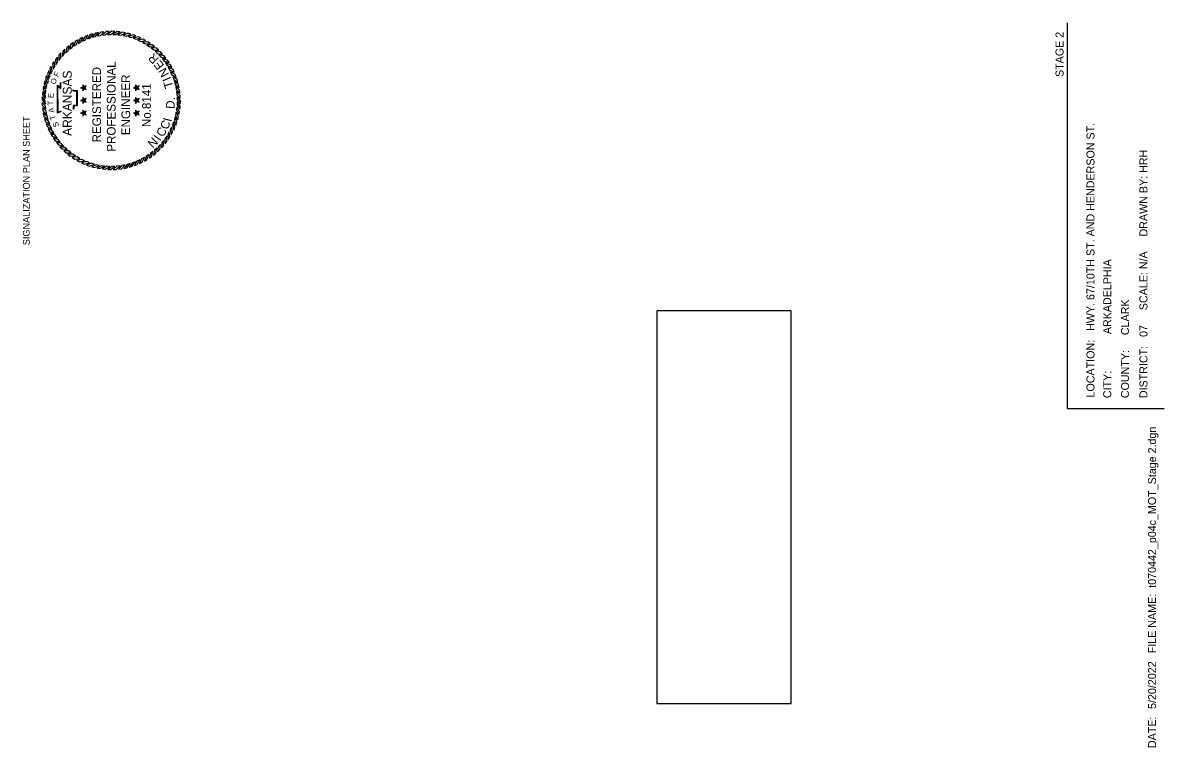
# Model space of a CAD drawing. Extents: x 610547 to 611161, y 419122 to 420064.
# Drawn here: x 610558 to 611161, y 419682 to 420064 of the extents above; entities that cross this region are included whole.
import ezdxf

# ---------------------------------------------------------------- set-up
doc = ezdxf.new("R2010")
doc.units = 0
for name, color, linetype in [('G-ANNO-SYMB', 7, 'Continuous'), ('G-ANNO-TEXT', 7, 'Continuous'), ('Level 10', 7, 'Continuous'), ('Level 57', 7, 'Continuous'), ('No Plot', 7, 'Continuous')]:
    doc.layers.add(name, color=color, linetype=linetype)

msp = doc.modelspace()

# ---------------------------------------------------------------- linework, layer by layer
at = {"layer": 'G-ANNO-SYMB'}
for points in [[(610592.78, 420057.58), (610591.32, 420057.02), (610589.94, 420054.58), (610591.48, 420055.28)], [(610595.51, 420058.43), (610594.01, 420057.99), (610592.45, 420055.67), (610594.04, 420056.25)], [(610598.31, 420059.07), (610596.77, 420058.75), (610595.03, 420056.56), (610596.67, 420057.01)], [(610601.14, 420059.49), (610599.58, 420059.29), (610597.68, 420057.24), (610599.34, 420057.56)], [(610604, 420059.68), (610602.43, 420059.6), (610600.37, 420057.72), (610602.05, 420057.9)], [(610606.86, 420059.65), (610605.29, 420059.7), (610603.09, 420057.98), (610604.78, 420058.03)], [(610609.71, 420059.4), (610608.15, 420059.56), (610605.82, 420058.02), (610607.52, 420057.94)], [(610612.54, 420058.92), (610611, 420059.21), (610608.55, 420057.85), (610610.23, 420057.64)], [(610615.32, 420058.22), (610613.8, 420058.63), (610611.26, 420057.47), (610612.92, 420057.13)], [(610618.03, 420057.31), (610616.55, 420057.83), (610613.93, 420056.88), (610615.55, 420056.4)], [(610582.77, 420052.11), (610581.54, 420051.12), (610580.99, 420048.38), (610582.24, 420049.52)], [(610585.1, 420053.77), (610583.81, 420052.88), (610583.04, 420050.19), (610584.37, 420051.23)], [(610587.56, 420055.24), (610586.2, 420054.45), (610585.22, 420051.84), (610586.64, 420052.77)], [(610590.12, 420056.51), (610588.71, 420055.84), (610587.53, 420053.3), (610589.01, 420054.12)], [(610620.66, 420056.18), (610619.23, 420056.82), (610616.54, 420056.08), (610618.12, 420055.48)], [(610623.2, 420054.85), (610621.82, 420055.61), (610619.08, 420055.07), (610620.61, 420054.35)], [(610625.63, 420053.33), (610624.31, 420054.19), (610621.54, 420053.87), (610623.01, 420053.03)], [(610627.93, 420051.62), (610626.68, 420052.58), (610623.89, 420052.48), (610625.29, 420051.53)], [(610576.64, 420046.11), (610575.68, 420044.87), (610575.78, 420042.07), (610576.73, 420043.47)], [(610578.52, 420048.27), (610577.47, 420047.1), (610577.35, 420044.31), (610578.41, 420045.63)], [(610580.57, 420050.27), (610579.43, 420049.19), (610579.09, 420046.42), (610580.25, 420047.65)], [(610630.08, 420049.74), (610628.92, 420050.79), (610626.13, 420050.92), (610627.45, 420049.86)], [(610632.09, 420047.69), (610631.01, 420048.83), (610628.24, 420049.18), (610629.47, 420048.02)], [(610633.92, 420045.5), (610632.94, 420046.72), (610630.2, 420047.28), (610631.34, 420046.02)], [(610573.41, 420041.38), (610572.66, 420040.01), (610573.19, 420037.26), (610573.91, 420038.8)], [(610574.93, 420043.81), (610574.07, 420042.5), (610574.39, 420039.72), (610575.23, 420041.19)], [(610635.58, 420043.16), (610634.7, 420044.46), (610632.01, 420045.23), (610633.05, 420043.89)], [(610637.05, 420040.7), (610636.27, 420042.06), (610633.65, 420043.04), (610634.58, 420041.63)], [(610638.33, 420038.14), (610637.65, 420039.56), (610635.12, 420040.74), (610635.94, 420039.25)], [(610570.04, 420033.5), (610569.63, 420031.98), (610570.79, 420029.44), (610571.14, 420031.1)], [(610570.96, 420036.21), (610570.43, 420034.73), (610571.39, 420032.11), (610571.86, 420033.74)], [(610572.08, 420038.85), (610571.44, 420037.41), (610572.19, 420034.72), (610572.78, 420036.31)], [(610639.39, 420035.48), (610638.83, 420036.95), (610636.4, 420038.32), (610637.1, 420036.78)], [(610640.25, 420032.75), (610639.81, 420034.25), (610637.49, 420035.82), (610638.06, 420034.22)], [(610568.87, 420027.9), (610568.7, 420026.34), (610570.24, 420024.01), (610570.32, 420025.7)], [(610569.34, 420030.72), (610569.05, 420029.18), (610570.41, 420026.73), (610570.62, 420028.41)], [(610590.52, 420029.89), (610590, 420030.27), (610588.85, 420029.89), (610590, 420029.52)], [(610590.52, 420029.89), (610590.71, 420030.5), (610590, 420031.48), (610590, 420030.27)], [(610590.52, 420029.89), (610590, 420029.52), (610590, 420028.31), (610590.71, 420029.29)], [(610590.52, 420029.89), (610591.15, 420029.89), (610591.86, 420030.87), (610590.71, 420030.5)], [(610590.52, 420029.89), (610590.71, 420029.29), (610591.86, 420028.91), (610591.15, 420029.89)], [(610618.45, 420029.89), (610617.93, 420030.27), (610616.78, 420029.89), (610617.93, 420029.52)], [(610618.45, 420029.89), (610618.64, 420030.5), (610617.93, 420031.48), (610617.93, 420030.27)], [(610618.45, 420029.89), (610617.93, 420029.52), (610617.93, 420028.31), (610618.64, 420029.29)], [(610618.45, 420029.89), (610619.08, 420029.89), (610619.79, 420030.87), (610618.64, 420030.5)], [(610618.45, 420029.89), (610618.64, 420029.29), (610619.79, 420028.91), (610619.08, 420029.89)], [(610640.89, 420029.96), (610640.57, 420031.49), (610638.38, 420033.23), (610638.83, 420031.6)], [(610641.31, 420027.12), (610641.1, 420028.68), (610639.06, 420030.58), (610639.38, 420028.92)], [(610641.5, 420024.27), (610641.42, 420025.83), (610639.53, 420027.89), (610639.72, 420026.21)], [(610568.61, 420025.04), (610568.57, 420023.48), (610570.29, 420021.27), (610570.23, 420022.97)], [(610568.58, 420022.18), (610568.66, 420020.61), (610570.55, 420018.55), (610570.36, 420020.24)], [(610590.52, 420023.22), (610590, 420023.6), (610588.85, 420023.22), (610590, 420022.85)], [(610590.52, 420023.22), (610590.71, 420023.83), (610590, 420024.81), (610590, 420023.6)], [(610590.52, 420023.22), (610590, 420022.85), (610590, 420021.64), (610590.71, 420022.62)], [(610590.52, 420023.22), (610591.15, 420023.22), (610591.86, 420024.2), (610590.71, 420023.83)], [(610590.52, 420023.22), (610590.71, 420022.62), (610591.86, 420022.24), (610591.15, 420023.22)], [(610618.45, 420023.22), (610617.93, 420023.6), (610616.78, 420023.22), (610617.93, 420022.85)], [(610618.45, 420023.22), (610618.64, 420023.83), (610617.93, 420024.81), (610617.93, 420023.6)], [(610618.45, 420023.22), (610617.93, 420022.85), (610617.93, 420021.64), (610618.64, 420022.62)], [(610618.45, 420023.22), (610619.08, 420023.22), (610619.79, 420024.2), (610618.64, 420023.83)], [(610618.45, 420023.22), (610618.64, 420022.62), (610619.79, 420022.24), (610619.08, 420023.22)], [(610641.21, 420018.55), (610641.38, 420020.11), (610639.84, 420022.44), (610639.76, 420020.75)], [(610641.47, 420021.4), (610641.51, 420022.97), (610639.79, 420025.17), (610639.85, 420023.48)], [(610568.77, 420019.32), (610568.98, 420017.77), (610571.02, 420015.86), (610570.7, 420017.52)], [(610569.19, 420016.49), (610569.51, 420014.95), (610571.7, 420013.21), (610571.25, 420014.85)], [(610590.52, 420016.55), (610590, 420016.93), (610588.85, 420016.55), (610590, 420016.18)], [(610590.52, 420016.55), (610590.71, 420017.16), (610590, 420018.14), (610590, 420016.93)], [(610590.52, 420016.55), (610590, 420016.18), (610590, 420014.97), (610590.71, 420015.95)], [(610590.52, 420016.55), (610591.15, 420016.55), (610591.86, 420017.53), (610590.71, 420017.16)], [(610590.52, 420016.55), (610590.71, 420015.95), (610591.86, 420015.57), (610591.15, 420016.55)], [(610618.45, 420016.55), (610617.93, 420016.93), (610616.78, 420016.55), (610617.93, 420016.18)], [(610618.45, 420016.55), (610618.64, 420017.16), (610617.93, 420018.14), (610617.93, 420016.93)], [(610618.45, 420016.55), (610617.93, 420016.18), (610617.93, 420014.97), (610618.64, 420015.95)], [(610618.45, 420016.55), (610619.08, 420016.55), (610619.79, 420017.53), (610618.64, 420017.16)], [(610618.45, 420016.55), (610618.64, 420015.95), (610619.79, 420015.57), (610619.08, 420016.55)], [(610640.04, 420012.95), (610640.45, 420014.46), (610639.29, 420017.01), (610638.94, 420015.35)], [(610640.74, 420015.72), (610641.03, 420017.27), (610639.67, 420019.71), (610639.46, 420018.03)], [(610569.83, 420013.7), (610570.27, 420012.19), (610572.59, 420010.63), (610572.02, 420012.22)], [(610570.69, 420010.96), (610571.25, 420009.5), (610573.68, 420008.12), (610572.98, 420009.67)], [(610638, 420007.6), (610638.64, 420009.03), (610637.89, 420011.72), (610637.3, 420010.14)], [(610639.12, 420010.23), (610639.65, 420011.71), (610638.69, 420014.34), (610638.22, 420012.71)], [(610571.75, 420008.31), (610572.43, 420006.89), (610574.96, 420005.71), (610574.14, 420007.19)], [(610573.03, 420005.74), (610573.81, 420004.38), (610576.43, 420003.4), (610575.5, 420004.82)], [(610574.5, 420003.28), (610575.38, 420001.99), (610578.07, 420001.22), (610577.03, 420002.56)], [(610633.44, 420000.34), (610634.4, 420001.58), (610634.3, 420004.37), (610633.35, 420002.97)], [(610635.15, 420002.64), (610636.01, 420003.95), (610635.69, 420006.73), (610634.85, 420005.25)], [(610636.67, 420005.06), (610637.42, 420006.44), (610636.89, 420009.18), (610636.17, 420007.65)], [(610576.16, 420000.95), (610577.14, 419999.73), (610579.88, 419999.17), (610578.74, 420000.42)], [(610577.99, 419998.75), (610579.07, 419997.61), (610581.84, 419997.27), (610580.61, 419998.43)], [(610627.31, 419994.34), (610628.54, 419995.32), (610629.09, 419998.06), (610627.84, 419996.92)], [(610629.51, 419996.18), (610630.65, 419997.25), (610630.99, 420000.03), (610629.83, 419998.79)], [(610631.56, 419998.18), (610632.61, 419999.34), (610632.73, 420002.13), (610631.67, 420000.81)], [(610580, 419996.7), (610581.16, 419995.65), (610583.95, 419995.53), (610582.63, 419996.59)], [(610582.15, 419994.82), (610583.4, 419993.86), (610586.19, 419993.96), (610584.79, 419994.91)], [(610584.45, 419993.11), (610585.77, 419992.26), (610588.54, 419992.57), (610587.07, 419993.41)], [(610586.88, 419991.59), (610588.26, 419990.84), (610591, 419991.37), (610589.47, 419992.09)], [(610617.3, 419988.87), (610618.76, 419989.43), (610620.14, 419991.86), (610618.6, 419991.16)], [(610619.96, 419989.94), (610621.37, 419990.61), (610622.55, 419993.14), (610621.07, 419992.33)], [(610622.52, 419991.21), (610623.88, 419991.99), (610624.86, 419994.61), (610623.44, 419993.68)], [(610624.98, 419992.68), (610626.27, 419993.57), (610627.04, 419996.25), (610625.71, 419995.21)], [(610589.42, 419990.26), (610590.85, 419989.62), (610593.54, 419990.37), (610591.96, 419990.97)], [(610592.05, 419989.14), (610593.53, 419988.61), (610596.15, 419989.57), (610594.53, 419990.04)], [(610594.76, 419988.22), (610596.28, 419987.82), (610598.82, 419988.97), (610597.16, 419989.32)], [(610597.54, 419987.53), (610599.08, 419987.24), (610601.53, 419988.59), (610599.85, 419988.8)], [(610600.37, 419987.05), (610601.93, 419986.88), (610604.26, 419988.42), (610602.56, 419988.5)], [(610603.22, 419986.79), (610604.79, 419986.75), (610606.99, 419988.47), (610605.3, 419988.42)], [(610606.08, 419986.76), (610607.65, 419986.84), (610609.71, 419988.73), (610608.03, 419988.54)], [(610608.94, 419986.96), (610610.5, 419987.16), (610612.4, 419989.2), (610610.74, 419988.88)], [(610611.77, 419987.37), (610613.31, 419987.7), (610615.05, 419989.88), (610613.41, 419989.44)], [(610614.57, 419988.01), (610616.07, 419988.46), (610617.63, 419990.77), (610616.04, 419990.2)]]:
    msp.add_lwpolyline(points, close=True, dxfattribs=at)
for points in [[(610578.57, 420017.38), (610576.73, 420016.53), (610576.72, 420031.24), (610578.26, 420030.01), (610578.25, 420031.01), (610578.24, 420031.85), (610578.33, 420032.68)], [(610578.47, 420017.59), (610576.96, 420016.89), (610576.95, 420030.76), (610578.5, 420029.52), (610578.48, 420031.01), (610578.47, 420031.84), (610578.56, 420032.66)], [(610584.55, 420028.78), (610584.8, 420028.47), (610585.2, 420028.36), (610585.99, 420028.27), (610586.79, 420028.27), (610586.79, 420020.53), (610585.65, 420020.53), (610585.17, 420020.53), (610585.01, 420019.99), (610585.01, 420018.92), (610584.8, 420018.78)], [(610584.73, 420028.92), (610584.94, 420028.67), (610585.24, 420028.59), (610586, 420028.51), (610587.02, 420028.51), (610587.02, 420020.29), (610585.65, 420020.29), (610585.34, 420020.29), (610585.24, 420019.96), (610585.24, 420018.79), (610584.92, 420018.58)]]:
    msp.add_lwpolyline(points, dxfattribs=at)
at = {"layer": 'Level 57'}
for points in [[(611109.39, 420064.17), (611109.39, 419860.59)], [(611109.39, 419860.59), (611160.6, 419860.59)]]:
    msp.add_lwpolyline(points, dxfattribs=at)
at = {"layer": 'No Plot'}
msp.add_lwpolyline([(610963.71, 419704.95), (610963.71, 419912.24), (610892.87, 419912.24), (610892.87, 419704.95)], close=True, dxfattribs=at)

# ---------------------------------------------------------------- texts
at = {"layer": 'G-ANNO-SYMB'}
for s, height, rotation, p in [('R', 4.59, 135.47796, (610630.44, 420045.31)), ('REGISTERED', 4.585, 90, (610599.66, 420001.06)), ('PROFESSIONAL', 4.5855, 90, (610607.33, 419996.15)), ('E', 4.59, 127.64979, (610633.21, 420041.65)), ('N', 4.59, 118.7033, (610635.74, 420037.04)), ('O', 2.9, 71.2218, (610575.53, 420031.44)), ('F', 2.9, 65.36282, (610577.06, 420035.35)), ('ARKANSAS', 4.737, 90, (610584.2, 420004.5)), ('ENGINEER', 4.585, 90, (610615, 420004.88)), ('I', 4.59, 114.23006, (610636.72, 420034.61)), ('No.8141', 4.567, 90, (610625.93, 420009.16)), ('T', 4.59, 106.77466, (610637.93, 420030.4)), ('T', 2.9, 91.47887, (610574.45, 420020.68)), ('E', 2.9, 86.67203, (610574.54, 420024.39)), ('D', 4.59, 86.64507, (610638.39, 420018.64)), ('.', 4.59, 94.84601, (610638.7, 420023.45)), ('A', 2.9, 98.67877, (610575.03, 420016.93)), ('T', 2.9, 106.90148, (610575.95, 420013.41)), ('S', 2.9, 109.77256, (610577.6, 420009.72)), ('C', 4.59, 66.51548, (610634.78, 420007.45)), ('I', 4.59, 74.34365, (610636.65, 420011.64)), ('N', 4.59, 45.26758, (610627.04, 419997.74)), ('I', 4.59, 54.21406, (610630.73, 420001.47)), ('C', 4.59, 58.68731, (610632.35, 420003.54))]:
    msp.add_text(s, height=height, rotation=rotation, dxfattribs=at).set_placement(p)
at = {"layer": 'G-ANNO-TEXT'}
msp.add_text('SIGNALIZATION PLAN SHEET', height=3.6, rotation=90, dxfattribs=at).set_placement((610562.05, 419946.83))
at = {"layer": 'Level 10'}
for s, p in [('STAGE 2', (611107.5, 420035.59)), ('LOCATION:   HWY. 67/10TH ST. AND HENDERSON ST.', (611123.82, 419866.48)), ('DISTRICT:   07     SCALE: N/A     DRAWN BY: HRH', (611151.77, 419866.13)), ('ARKADELPHIA ', (611132.67, 419899.9)), ('COUNTY:     CLARK', (611142.05, 419866.13)), ('CITY:       ', (611132.67, 419866.13)), ('t070442_p04c_MOT_Stage 2.dgn', (611156.31, 419766.06)), ('  FILE NAME: ', (611156.31, 419728.38)), ('5/20/2022', (611156.31, 419702.15)), ('DATE:  ', (611156.31, 419681.51))]:
    msp.add_text(s, height=4.221, rotation=90, dxfattribs=at).set_placement(p)

doc.saveas('drawing.dxf')
